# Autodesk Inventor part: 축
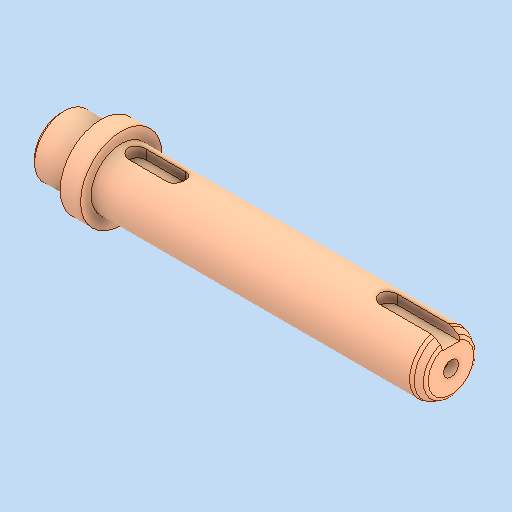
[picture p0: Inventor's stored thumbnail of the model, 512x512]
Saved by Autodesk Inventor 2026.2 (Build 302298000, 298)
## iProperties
Created: 2026-01
Part Number: 축
Material: 강철, 탄소
Document SubType Name: Modeling
Designer: PC2-07
Density: 7.85 g/cm^3
Appearance: 기본값
Author: jhkim
Sending System: Autodesk Inventor 2026
Preprocessor: ST-DEVELOPER v20.1
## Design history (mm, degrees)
feature "솔리드1"
node "솔리드2"
